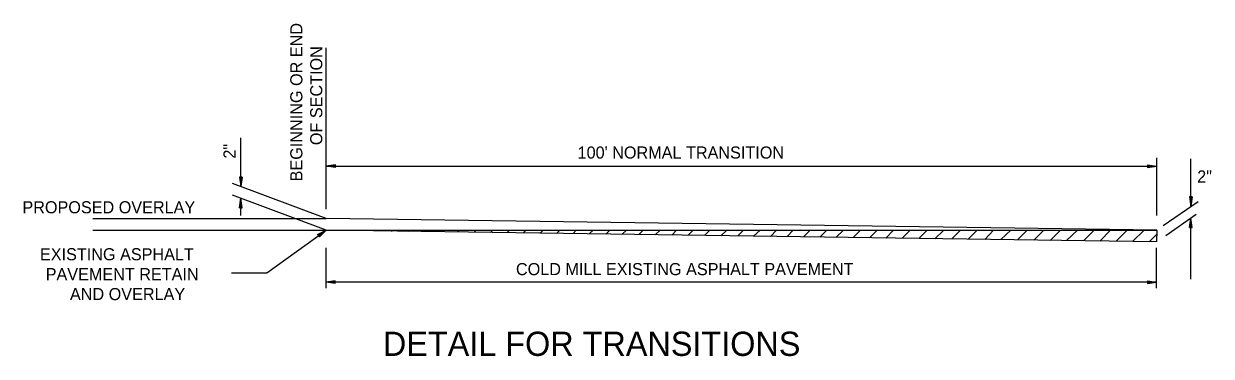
# Model space of a CAD drawing. Extents: x 836 to 5683, y -463 to 1545.
# Drawn here: x 2891 to 3479, y 687 to 851 of the extents above; entities that cross this region are included whole.
import ezdxf

# ---------------------------------------------------------------- set-up
doc = ezdxf.new("R2010")
doc.units = 0
doc.layers.add('Default', color=7, linetype='Continuous')

msp = doc.modelspace()

# ---------------------------------------------------------------- linework, layer by layer
at = {"layer": 'Default'}
for p, q in [((3040.45, 759.62), (3040.45, 839.48)), ((2998.25, 770.96), (2998.25, 794.95)), ((3452.01, 756.52), (3452.01, 784.94)), ((3468.87, 760.96), (3468.87, 784.49)), ((3045.11, 781.62), (3040.44, 780.95)), ((3040.44, 780.95), (3452.01, 780.95)), ((3045.11, 780.29), (3040.44, 780.95)), ((3045.11, 781.4), (3041.12, 780.95)), ((3045.11, 780.29), (3041.12, 780.95)), ((3045.11, 781.4), (3042.01, 780.95)), ((3045.11, 780.51), (3042.01, 780.95)), ((3045.11, 781.17), (3042.9, 780.95)), ((3045.11, 780.51), (3042.9, 780.95)), ((3045.11, 781.17), (3043.56, 780.95)), ((3045.11, 780.74), (3043.56, 780.95)), ((3045.11, 780.95), (3044.45, 780.95)), ((3045.11, 780.74), (3044.45, 780.95)), ((3045.11, 780.29), (3045.11, 781.62)), ((3447.33, 781.62), (3452.01, 780.95)), ((3447.33, 781.62), (3447.33, 780.29)), ((3447.33, 781.4), (3450.45, 780.95)), ((3447.33, 781.4), (3451.1, 780.95)), ((3447.33, 781.17), (3448.89, 780.95)), ((3447.33, 781.17), (3449.56, 780.95)), ((3447.33, 780.29), (3452.01, 780.95)), ((3447.33, 780.74), (3448.89, 780.95)), ((3447.33, 780.51), (3450.45, 780.95)), ((3447.33, 780.29), (3451.1, 780.95)), ((3447.33, 780.51), (3449.56, 780.95)), ((3447.33, 780.74), (3448, 780.95)), ((3447.33, 780.95), (3448, 780.95)), ((3040.44, 754.96), (2994.04, 772.29)), ((2997.58, 775.41), (2998.25, 770.96)), ((2997.58, 775.41), (2998.25, 771.62)), ((2998.92, 775.41), (2997.58, 775.41)), ((2997.81, 775.41), (2998.25, 772.52)), ((2997.81, 775.41), (2998.25, 773.17)), ((2998.03, 775.41), (2998.25, 774.07)), ((2998.03, 775.41), (2998.25, 774.73)), ((2998.92, 775.41), (2998.25, 770.96)), ((2998.47, 775.41), (2998.25, 774.07)), ((2998.7, 775.41), (2998.25, 772.52)), ((2998.7, 775.41), (2998.25, 771.62)), ((2998.47, 775.41), (2998.25, 773.17)), ((2998.25, 775.41), (2998.25, 774.73)), ((3040.44, 749.2), (2994.04, 766.52)), ((2997.58, 760.29), (2998.25, 764.96)), ((2998.92, 760.29), (2998.25, 764.96)), ((2998.25, 756.52), (2998.25, 764.96)), ((3468.21, 765.62), (3468.87, 760.96)), ((3469.54, 765.62), (3468.21, 765.62)), ((3468.44, 765.62), (3468.87, 762.52)), ((3468.44, 765.62), (3468.87, 761.85)), ((3468.65, 765.62), (3468.87, 764.08)), ((3468.65, 765.62), (3468.87, 763.41)), ((3469.54, 765.62), (3468.87, 760.96)), ((3469.09, 765.62), (3468.87, 764.08)), ((3469.32, 765.62), (3468.87, 762.52)), ((3469.54, 765.62), (3468.87, 761.85)), ((3469.32, 765.62), (3468.87, 763.41)), ((3468.87, 765.62), (3468.87, 764.96)), ((3469.09, 765.62), (3468.87, 764.96)), ((2997.58, 760.29), (2998.25, 764.29)), ((2997.58, 760.29), (2998.92, 760.29)), ((2997.81, 760.29), (2998.25, 763.41)), ((2997.81, 760.29), (2998.25, 762.75)), ((2998.03, 760.29), (2998.25, 761.85)), ((2998.03, 760.29), (2998.25, 760.96)), ((2998.7, 760.29), (2998.25, 764.29)), ((2998.7, 760.29), (2998.25, 763.41)), ((2998.47, 760.29), (2998.25, 762.75)), ((2998.47, 760.29), (2998.25, 761.85)), ((2998.25, 760.29), (2998.25, 760.96)), ((3455.11, 751.42), (3472.42, 763.41)), ((2924.97, 754.96), (3040.45, 754.96)), ((3452.01, 749.2), (3040.44, 754.96)), ((3456.44, 746.53), (3471.54, 757.18)), ((3468.21, 750.52), (3468.87, 755.19)), ((3468.44, 750.52), (3468.87, 754.52)), ((3468.44, 750.52), (3468.87, 753.63)), ((3468.87, 724.98), (3468.87, 755.19)), ((3469.54, 750.52), (3468.87, 755.19)), ((3469.54, 750.52), (3468.87, 754.52)), ((3469.32, 750.52), (3468.87, 753.63)), ((2924.97, 749.19), (3452.01, 749.19)), ((3011.14, 728.1), (3040.44, 749.2)), ((3036.23, 746.96), (3040.44, 749.2)), ((3036.46, 746.96), (3039.79, 748.75)), ((3036.46, 746.96), (3039.12, 748.3)), ((3036.46, 746.75), (3038.44, 747.85)), ((3036.46, 746.75), (3038.01, 747.42)), ((3036.9, 746.08), (3039.12, 748.3)), ((3036.9, 746.31), (3038.44, 747.85)), ((3036.9, 746.31), (3038.01, 747.42)), ((3037.11, 745.86), (3040.44, 749.2)), ((3037.11, 746.08), (3039.79, 748.75)), ((3451.77, 743.41), (3040.44, 749.2)), ((3056.65, 748.96), (3056.88, 749.2)), ((3064.76, 748.86), (3065.1, 749.2)), ((3072.87, 748.74), (3073.53, 749.2)), ((3081.18, 748.62), (3081.77, 749.2)), ((3089.3, 748.51), (3089.98, 749.2)), ((3097.41, 748.39), (3098.2, 749.2)), ((3105.52, 748.28), (3106.41, 749.2)), ((3113.81, 748.16), (3114.85, 749.2)), ((3121.92, 748.05), (3123.08, 749.2)), ((3130.24, 747.93), (3131.29, 749.2)), ((3138.14, 747.82), (3139.51, 749.2)), ((3146.47, 747.7), (3147.95, 749.2)), ((3154.56, 747.59), (3156.18, 749.2)), ((3162.87, 747.47), (3164.39, 749.2)), ((3170.76, 747.36), (3172.83, 749.2)), ((3179.1, 747.25), (3181.04, 749.2)), ((3187.21, 747.13), (3189.26, 749.2)), ((3195.31, 747), (3197.49, 749.18)), ((3203.41, 746.9), (3205.91, 749.2)), ((3211.73, 746.79), (3214.13, 749.2)), ((3219.83, 746.67), (3222.35, 749.2)), ((3227.94, 746.56), (3230.56, 749.2)), ((3236.03, 746.45), (3239, 749.2)), ((3244.36, 746.33), (3247.22, 749.2)), ((3252.23, 746.21), (3255.44, 749.2)), ((3260.57, 746.1), (3263.66, 749.2)), ((3268.89, 745.98), (3271.88, 749.2)), ((3276.99, 745.86), (3280.31, 749.2)), ((3285.1, 745.75), (3288.53, 749.2)), ((3293.21, 745.64), (3296.75, 749.2)), ((3301.54, 745.53), (3305.2, 749.2)), ((3309.64, 745.41), (3313.41, 749.2)), ((3317.74, 745.29), (3321.63, 749.2)), ((3325.84, 745.18), (3329.84, 749.2)), ((3334.16, 745.06), (3338.28, 749.2)), ((3342.05, 744.95), (3346.5, 749.2)), ((3350.37, 744.84), (3354.72, 749.2)), ((3358.48, 744.72), (3362.93, 749.2)), ((3366.79, 744.61), (3371.16, 749.2)), ((3374.67, 744.49), (3379.6, 749.2)), ((3382.99, 744.38), (3387.81, 749.2)), ((3391.15, 744.3), (3396.03, 749.2)), ((3399.21, 744.15), (3404.25, 749.2)), ((3407.31, 744.04), (3412.69, 749.2)), ((3415.63, 743.92), (3420.9, 749.2)), ((3423.74, 743.81), (3429.13, 749.2)), ((3431.85, 743.69), (3437.33, 749.2)), ((3439.94, 743.58), (3445.78, 749.2)), ((3452.01, 749.2), (3451.77, 743.41)), ((3468.21, 750.52), (3469.54, 750.52)), ((3468.65, 750.52), (3468.87, 752.96)), ((3468.65, 750.52), (3468.87, 752.07)), ((3469.32, 750.52), (3468.87, 752.96)), ((3469.09, 750.52), (3468.87, 752.07)), ((3469.09, 750.52), (3468.87, 751.42)), ((3468.87, 750.52), (3468.87, 751.42)), ((3036.23, 746.96), (3037.11, 745.86)), ((3036.68, 746.53), (3037.34, 746.96)), ((3036.68, 746.53), (3037.34, 746.96)), ((3448.27, 743.46), (3451.92, 747.1)), ((3040.44, 720.53), (3040.44, 740.52)), ((3451.77, 720.53), (3451.77, 740.52)), ((2993.6, 728.1), (3011.14, 728.1)), ((3044.91, 724.09), (3040.44, 723.43)), ((3044.91, 724.09), (3040.44, 723.43)), ((3044.91, 724.09), (3041.12, 723.43)), ((3044.91, 724.09), (3041.12, 723.43)), ((3044.91, 723.88), (3042.01, 723.43)), ((3044.91, 723.88), (3042.01, 723.43)), ((3044.91, 723.88), (3042.67, 723.43)), ((3044.91, 723.88), (3042.67, 723.43)), ((3044.91, 723.64), (3043.56, 723.43)), ((3044.91, 723.64), (3043.56, 723.43)), ((3044.91, 723.64), (3044.23, 723.43)), ((3044.91, 723.64), (3044.23, 723.43)), ((3044.91, 722.76), (3044.91, 724.09)), ((3044.91, 722.76), (3044.91, 724.09)), ((3447.33, 724.09), (3451.77, 723.43)), ((3447.33, 724.09), (3451.1, 723.43)), ((3447.33, 724.09), (3447.33, 722.76)), ((3447.33, 723.88), (3450.22, 723.43)), ((3447.33, 723.88), (3449.56, 723.43)), ((3447.33, 723.64), (3448.67, 723.43)), ((3447.33, 723.64), (3448, 723.43)), ((3451.77, 723.43), (3040.44, 723.43)), ((3044.91, 722.76), (3040.44, 723.43)), ((3044.91, 722.76), (3040.44, 723.43)), ((3044.91, 722.98), (3041.12, 723.43)), ((3044.91, 722.98), (3041.12, 723.43)), ((3044.91, 722.98), (3042.01, 723.43)), ((3044.91, 722.98), (3042.01, 723.43)), ((3044.91, 723.21), (3042.67, 723.43)), ((3044.91, 723.21), (3042.67, 723.43)), ((3044.91, 723.21), (3043.56, 723.43)), ((3044.91, 723.21), (3043.56, 723.43)), ((3044.91, 723.43), (3044.23, 723.43)), ((3044.91, 723.43), (3044.23, 723.43)), ((3447.33, 722.76), (3451.77, 723.43)), ((3447.33, 723.21), (3448.67, 723.43)), ((3447.33, 722.98), (3450.22, 723.43)), ((3447.33, 722.98), (3451.1, 723.43)), ((3447.33, 723.21), (3449.56, 723.43)), ((3447.33, 723.43), (3448, 723.43))]:
    msp.add_line(p, q, dxfattribs=at)

# ---------------------------------------------------------------- texts
for s, p in [('BEGINNING OR END', (3028.71, 773.35)), ('OF SECTION', (3038.58, 791.29)), ('2"', (2995.59, 784.62))]:
    msp.add_text(s, height=6, rotation=90, dxfattribs=at).set_placement(p)
for s, height, p in [("100' NORMAL TRANSITION", 6, (3165.05, 784.64)), ('2"', 6, (3472, 772.79)), ('PROPOSED OVERLAY', 6, (2890.01, 757.53)), ('EXISTING ASPHALT', 6, (2898.7, 734.26)), ('PAVEMENT RETAIN', 6, (2901.53, 724.4)), ('COLD MILL EXISTING ASPHALT PAVEMENT', 6, (3134.52, 726.9)), ('AND OVERLAY', 6, (2913.57, 714.54)), ('DETAIL FOR TRANSITIONS', 12, (3068.59, 686.91))]:
    msp.add_text(s, height=height, dxfattribs=at).set_placement(p)

doc.saveas('drawing.dxf')
